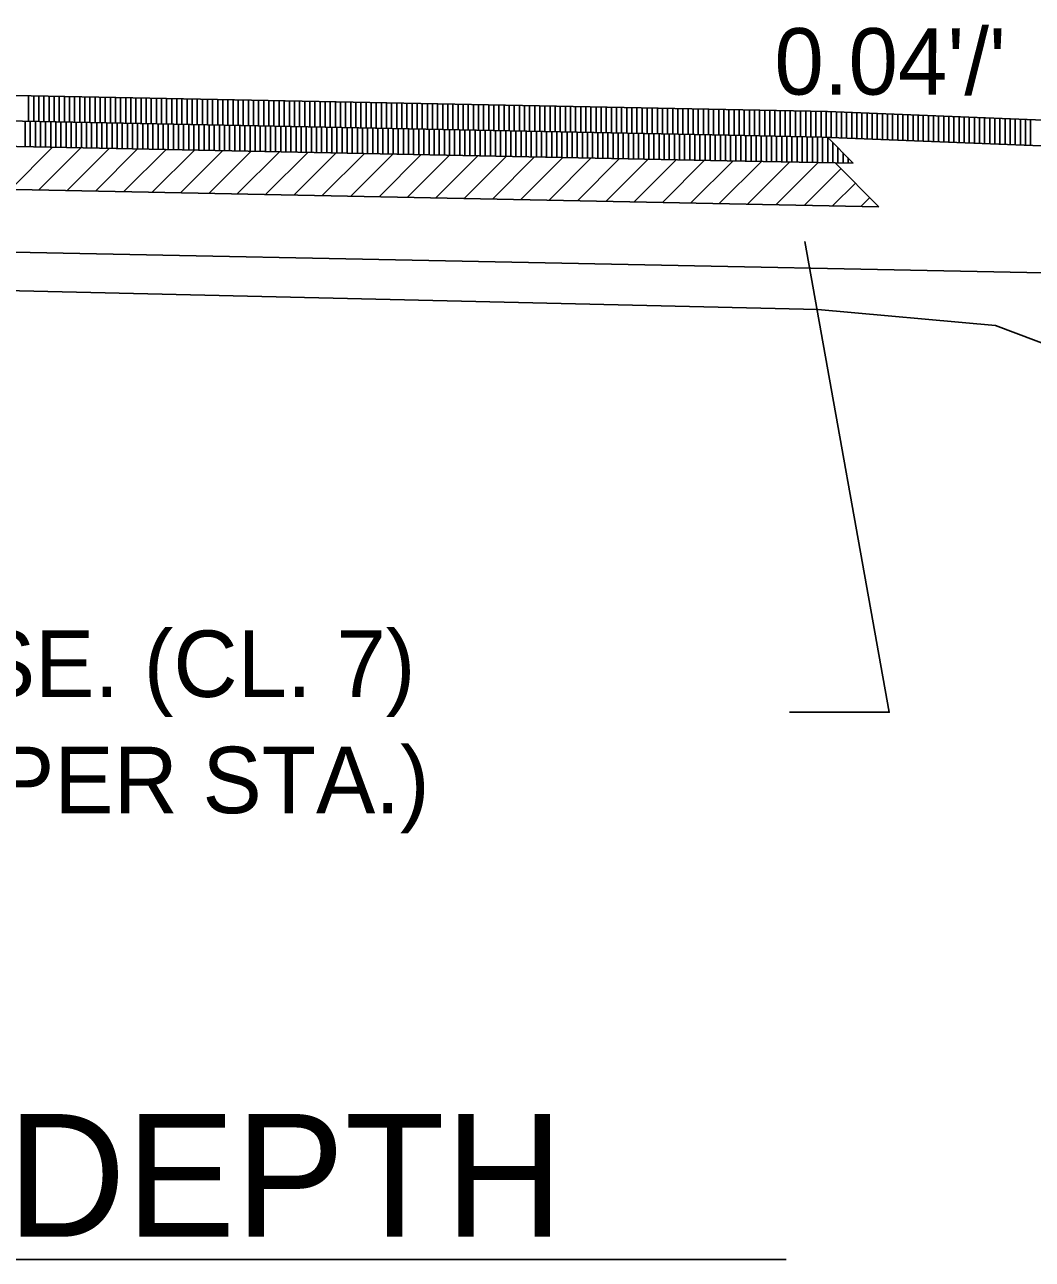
# Model space of a CAD drawing. Extents: x 1373719 to 1374161, y 379835 to 380167.
# Drawn here: x 1373967.86 to 1373977.71, y 380049.16 to 380061.24 of the extents above; entities that cross this region are included whole.
import ezdxf

# ---------------------------------------------------------------- set-up
doc = ezdxf.new("R2010")
doc.units = 0
for name, color, linetype in [('ACHM Surface', 7, 'Continuous'), ('Agg Base Course Text', 7, 'Continuous'), ('Binder', 7, 'Continuous'), ('GREEN_TXT', 7, 'Continuous'), ('T_Drafting', 7, 'Continuous')]:
    doc.layers.add(name, color=color, linetype=linetype)

msp = doc.modelspace()

# ---------------------------------------------------------------- linework, layer by layer
for p, q in [((1373964.712, 380060.605), (1373975.71, 380060.386)), ((1373975.71, 380060.386), (1373979.707, 380060.226)), ((1373975.711, 380060.135), (1373975.964, 380059.881)), ((1373975.785, 380059.885), (1373976.214, 380059.455)), ((1373964.691, 380059.072), (1373986.027, 380058.646))]:
    msp.add_line(p, q)
for points in [[(1373964.712, 380060.355), (1373974.743, 380060.155), (1373975.657, 380060.137), (1373977.8, 380060.052), (1373979.542, 380059.986)], [(1373964.712, 380060.105), (1373974.731, 380059.905), (1373975.964, 380059.881)], [(1373964.682, 380059.685), (1373976.214, 380059.455)]]:
    msp.add_lwpolyline(points)
at = {"layer": 'ACHM Surface'}
for p, q in [((1373967.898, 380060.292), (1373967.898, 380060.542)), ((1373967.948, 380060.291), (1373967.948, 380060.541)), ((1373967.998, 380060.29), (1373967.998, 380060.54)), ((1373968.048, 380060.289), (1373968.048, 380060.539)), ((1373968.098, 380060.288), (1373968.098, 380060.538)), ((1373968.148, 380060.287), (1373968.148, 380060.537)), ((1373968.198, 380060.286), (1373968.198, 380060.536)), ((1373968.248, 380060.285), (1373968.248, 380060.535)), ((1373968.298, 380060.284), (1373968.298, 380060.534)), ((1373968.348, 380060.283), (1373968.348, 380060.533)), ((1373968.398, 380060.282), (1373968.398, 380060.532)), ((1373968.448, 380060.281), (1373968.448, 380060.531)), ((1373968.498, 380060.28), (1373968.498, 380060.53)), ((1373968.548, 380060.279), (1373968.548, 380060.529)), ((1373968.598, 380060.278), (1373968.598, 380060.528)), ((1373968.648, 380060.277), (1373968.648, 380060.527)), ((1373968.698, 380060.276), (1373968.698, 380060.526)), ((1373968.748, 380060.275), (1373968.748, 380060.525)), ((1373968.798, 380060.274), (1373968.798, 380060.524)), ((1373968.848, 380060.273), (1373968.848, 380060.523)), ((1373968.898, 380060.272), (1373968.898, 380060.522)), ((1373968.948, 380060.271), (1373968.948, 380060.521)), ((1373968.998, 380060.27), (1373968.998, 380060.52)), ((1373969.048, 380060.269), (1373969.048, 380060.519)), ((1373969.098, 380060.268), (1373969.098, 380060.518)), ((1373969.148, 380060.267), (1373969.148, 380060.517)), ((1373969.198, 380060.266), (1373969.198, 380060.516)), ((1373969.248, 380060.265), (1373969.248, 380060.515)), ((1373969.298, 380060.264), (1373969.298, 380060.514)), ((1373969.348, 380060.263), (1373969.348, 380060.513)), ((1373969.398, 380060.262), (1373969.398, 380060.512)), ((1373969.448, 380060.261), (1373969.448, 380060.511)), ((1373969.498, 380060.26), (1373969.498, 380060.51)), ((1373969.548, 380060.259), (1373969.548, 380060.509)), ((1373969.598, 380060.258), (1373969.598, 380060.508)), ((1373969.648, 380060.257), (1373969.648, 380060.507)), ((1373969.698, 380060.256), (1373969.698, 380060.506)), ((1373969.748, 380060.255), (1373969.748, 380060.505)), ((1373969.798, 380060.254), (1373969.798, 380060.504)), ((1373969.848, 380060.253), (1373969.848, 380060.503)), ((1373969.898, 380060.252), (1373969.898, 380060.502)), ((1373969.948, 380060.251), (1373969.948, 380060.501)), ((1373969.998, 380060.25), (1373969.998, 380060.5)), ((1373970.048, 380060.249), (1373970.048, 380060.499)), ((1373970.098, 380060.248), (1373970.098, 380060.498)), ((1373970.148, 380060.247), (1373970.148, 380060.497)), ((1373970.198, 380060.246), (1373970.198, 380060.496)), ((1373970.248, 380060.245), (1373970.248, 380060.495)), ((1373970.298, 380060.244), (1373970.298, 380060.494)), ((1373970.348, 380060.243), (1373970.348, 380060.493)), ((1373970.398, 380060.242), (1373970.398, 380060.492)), ((1373970.448, 380060.241), (1373970.448, 380060.491)), ((1373970.498, 380060.24), (1373970.498, 380060.49)), ((1373970.548, 380060.239), (1373970.548, 380060.489)), ((1373970.598, 380060.238), (1373970.598, 380060.488)), ((1373970.648, 380060.237), (1373970.648, 380060.487)), ((1373970.698, 380060.236), (1373970.698, 380060.486)), ((1373970.748, 380060.235), (1373970.748, 380060.485)), ((1373970.798, 380060.234), (1373970.798, 380060.484)), ((1373970.848, 380060.233), (1373970.848, 380060.483)), ((1373970.898, 380060.232), (1373970.898, 380060.482)), ((1373970.948, 380060.231), (1373970.948, 380060.481)), ((1373970.998, 380060.23), (1373970.998, 380060.48)), ((1373971.048, 380060.229), (1373971.048, 380060.479)), ((1373971.098, 380060.228), (1373971.098, 380060.478)), ((1373971.148, 380060.227), (1373971.148, 380060.477)), ((1373971.198, 380060.226), (1373971.198, 380060.476)), ((1373971.248, 380060.225), (1373971.248, 380060.475)), ((1373971.298, 380060.224), (1373971.298, 380060.474)), ((1373971.348, 380060.223), (1373971.348, 380060.473)), ((1373971.398, 380060.222), (1373971.398, 380060.472)), ((1373971.448, 380060.221), (1373971.448, 380060.471)), ((1373971.498, 380060.22), (1373971.498, 380060.47)), ((1373971.548, 380060.219), (1373971.548, 380060.469)), ((1373971.598, 380060.218), (1373971.598, 380060.468)), ((1373971.648, 380060.217), (1373971.648, 380060.467)), ((1373971.698, 380060.216), (1373971.698, 380060.466)), ((1373971.748, 380060.215), (1373971.748, 380060.465)), ((1373971.798, 380060.214), (1373971.798, 380060.464)), ((1373971.848, 380060.213), (1373971.848, 380060.463)), ((1373971.898, 380060.212), (1373971.898, 380060.462)), ((1373971.948, 380060.211), (1373971.948, 380060.461)), ((1373971.998, 380060.21), (1373971.998, 380060.46)), ((1373972.048, 380060.209), (1373972.048, 380060.459)), ((1373972.098, 380060.208), (1373972.098, 380060.458)), ((1373972.148, 380060.207), (1373972.148, 380060.457)), ((1373972.198, 380060.206), (1373972.198, 380060.456)), ((1373972.248, 380060.205), (1373972.248, 380060.455)), ((1373972.298, 380060.204), (1373972.298, 380060.454)), ((1373972.348, 380060.203), (1373972.348, 380060.453)), ((1373972.398, 380060.202), (1373972.398, 380060.452)), ((1373972.448, 380060.201), (1373972.448, 380060.451)), ((1373972.498, 380060.2), (1373972.498, 380060.45)), ((1373972.548, 380060.199), (1373972.548, 380060.449)), ((1373972.598, 380060.198), (1373972.598, 380060.448)), ((1373972.648, 380060.197), (1373972.648, 380060.447)), ((1373972.698, 380060.196), (1373972.698, 380060.446)), ((1373972.748, 380060.195), (1373972.748, 380060.445)), ((1373972.798, 380060.194), (1373972.798, 380060.444)), ((1373972.848, 380060.193), (1373972.848, 380060.443)), ((1373972.898, 380060.192), (1373972.898, 380060.442)), ((1373972.948, 380060.191), (1373972.948, 380060.441)), ((1373972.998, 380060.19), (1373972.998, 380060.44)), ((1373973.048, 380060.189), (1373973.048, 380060.439)), ((1373973.098, 380060.188), (1373973.098, 380060.438)), ((1373973.148, 380060.187), (1373973.148, 380060.437)), ((1373973.198, 380060.186), (1373973.198, 380060.436)), ((1373973.248, 380060.185), (1373973.248, 380060.435)), ((1373973.298, 380060.184), (1373973.298, 380060.434)), ((1373973.348, 380060.183), (1373973.348, 380060.433)), ((1373973.398, 380060.182), (1373973.398, 380060.432)), ((1373973.448, 380060.181), (1373973.448, 380060.431)), ((1373973.498, 380060.18), (1373973.498, 380060.43)), ((1373973.548, 380060.179), (1373973.548, 380060.429)), ((1373973.598, 380060.178), (1373973.598, 380060.428)), ((1373973.648, 380060.177), (1373973.648, 380060.427)), ((1373973.698, 380060.176), (1373973.698, 380060.426)), ((1373973.748, 380060.175), (1373973.748, 380060.425)), ((1373973.798, 380060.174), (1373973.798, 380060.424)), ((1373973.848, 380060.173), (1373973.848, 380060.423)), ((1373973.898, 380060.172), (1373973.898, 380060.422)), ((1373973.948, 380060.171), (1373973.948, 380060.421)), ((1373973.998, 380060.17), (1373973.998, 380060.42)), ((1373974.048, 380060.169), (1373974.048, 380060.419)), ((1373974.098, 380060.168), (1373974.098, 380060.418)), ((1373974.148, 380060.167), (1373974.148, 380060.417)), ((1373974.198, 380060.166), (1373974.198, 380060.416)), ((1373974.248, 380060.165), (1373974.248, 380060.415)), ((1373974.298, 380060.164), (1373974.298, 380060.414)), ((1373974.348, 380060.163), (1373974.348, 380060.413)), ((1373974.398, 380060.162), (1373974.398, 380060.412)), ((1373967.864, 380060.042), (1373967.864, 380060.293)), ((1373967.914, 380060.041), (1373967.914, 380060.292)), ((1373967.964, 380060.04), (1373967.964, 380060.291)), ((1373974.448, 380060.161), (1373974.448, 380060.411)), ((1373974.498, 380060.16), (1373974.498, 380060.41)), ((1373974.548, 380060.159), (1373974.548, 380060.409)), ((1373974.598, 380060.158), (1373974.598, 380060.408)), ((1373974.648, 380060.157), (1373974.648, 380060.407)), ((1373974.698, 380060.156), (1373974.698, 380060.406)), ((1373974.748, 380060.155), (1373974.748, 380060.405)), ((1373974.798, 380060.154), (1373974.798, 380060.404)), ((1373974.848, 380060.153), (1373974.848, 380060.403)), ((1373974.898, 380060.152), (1373974.898, 380060.402)), ((1373974.948, 380060.151), (1373974.948, 380060.401)), ((1373974.998, 380060.15), (1373974.998, 380060.4)), ((1373975.048, 380060.149), (1373975.048, 380060.399)), ((1373975.098, 380060.148), (1373975.098, 380060.398)), ((1373975.148, 380060.147), (1373975.148, 380060.397)), ((1373975.198, 380060.146), (1373975.198, 380060.396)), ((1373975.248, 380060.145), (1373975.248, 380060.395)), ((1373975.298, 380060.144), (1373975.298, 380060.394)), ((1373975.348, 380060.143), (1373975.348, 380060.393)), ((1373975.398, 380060.142), (1373975.398, 380060.392)), ((1373975.448, 380060.141), (1373975.448, 380060.391)), ((1373975.498, 380060.14), (1373975.498, 380060.39)), ((1373975.548, 380060.139), (1373975.548, 380060.389)), ((1373975.598, 380060.138), (1373975.598, 380060.388)), ((1373975.648, 380060.137), (1373975.648, 380060.387)), ((1373975.698, 380060.135), (1373975.698, 380060.386)), ((1373975.748, 380060.133), (1373975.748, 380060.384)), ((1373975.798, 380060.131), (1373975.798, 380060.382)), ((1373975.848, 380060.129), (1373975.848, 380060.38)), ((1373975.898, 380060.127), (1373975.898, 380060.378)), ((1373975.948, 380060.126), (1373975.948, 380060.376)), ((1373975.998, 380060.124), (1373975.998, 380060.374)), ((1373976.048, 380060.122), (1373976.048, 380060.372)), ((1373976.098, 380060.12), (1373976.098, 380060.37)), ((1373976.148, 380060.118), (1373976.148, 380060.368)), ((1373976.198, 380060.116), (1373976.198, 380060.366)), ((1373976.248, 380060.114), (1373976.248, 380060.364)), ((1373976.298, 380060.112), (1373976.298, 380060.362)), ((1373976.348, 380060.11), (1373976.348, 380060.36)), ((1373976.398, 380060.108), (1373976.398, 380060.358)), ((1373976.448, 380060.106), (1373976.448, 380060.356)), ((1373976.498, 380060.104), (1373976.498, 380060.354)), ((1373976.548, 380060.102), (1373976.548, 380060.352)), ((1373976.598, 380060.1), (1373976.598, 380060.35)), ((1373976.648, 380060.098), (1373976.648, 380060.348)), ((1373976.698, 380060.096), (1373976.698, 380060.346)), ((1373976.748, 380060.094), (1373976.748, 380060.344)), ((1373976.798, 380060.092), (1373976.798, 380060.342)), ((1373976.848, 380060.09), (1373976.848, 380060.34)), ((1373976.898, 380060.088), (1373976.898, 380060.338)), ((1373976.948, 380060.086), (1373976.948, 380060.336)), ((1373976.998, 380060.084), (1373976.998, 380060.334)), ((1373977.048, 380060.082), (1373977.048, 380060.332)), ((1373977.098, 380060.08), (1373977.098, 380060.33)), ((1373977.148, 380060.078), (1373977.148, 380060.328)), ((1373977.198, 380060.076), (1373977.198, 380060.326)), ((1373977.248, 380060.074), (1373977.248, 380060.324)), ((1373977.298, 380060.072), (1373977.298, 380060.322)), ((1373977.348, 380060.07), (1373977.348, 380060.32)), ((1373977.398, 380060.068), (1373977.398, 380060.318)), ((1373977.448, 380060.066), (1373977.448, 380060.316)), ((1373977.498, 380060.064), (1373977.498, 380060.314)), ((1373977.548, 380060.062), (1373977.548, 380060.312)), ((1373977.598, 380060.06), (1373977.598, 380060.31)), ((1373977.648, 380060.058), (1373977.648, 380060.308)), ((1373977.698, 380060.056), (1373977.698, 380060.306)), ((1373968.014, 380060.039), (1373968.014, 380060.29)), ((1373968.064, 380060.038), (1373968.064, 380060.289)), ((1373968.114, 380060.037), (1373968.114, 380060.288)), ((1373968.164, 380060.036), (1373968.164, 380060.287)), ((1373968.214, 380060.035), (1373968.214, 380060.286)), ((1373968.264, 380060.034), (1373968.264, 380060.285)), ((1373968.314, 380060.033), (1373968.314, 380060.284)), ((1373968.364, 380060.032), (1373968.364, 380060.283)), ((1373968.414, 380060.031), (1373968.414, 380060.282)), ((1373968.464, 380060.03), (1373968.464, 380060.281)), ((1373968.514, 380060.029), (1373968.514, 380060.28)), ((1373968.564, 380060.028), (1373968.564, 380060.279)), ((1373968.614, 380060.027), (1373968.614, 380060.278)), ((1373968.664, 380060.026), (1373968.664, 380060.277)), ((1373968.714, 380060.025), (1373968.714, 380060.276)), ((1373968.764, 380060.024), (1373968.764, 380060.275)), ((1373968.814, 380060.023), (1373968.814, 380060.274)), ((1373968.864, 380060.022), (1373968.864, 380060.273)), ((1373968.914, 380060.021), (1373968.914, 380060.272)), ((1373968.964, 380060.02), (1373968.964, 380060.271)), ((1373969.014, 380060.019), (1373969.014, 380060.27)), ((1373969.064, 380060.018), (1373969.064, 380060.269)), ((1373969.114, 380060.017), (1373969.114, 380060.268)), ((1373969.164, 380060.016), (1373969.164, 380060.267)), ((1373969.214, 380060.015), (1373969.214, 380060.266)), ((1373969.264, 380060.014), (1373969.264, 380060.265)), ((1373969.314, 380060.013), (1373969.314, 380060.264)), ((1373969.364, 380060.012), (1373969.364, 380060.263)), ((1373969.414, 380060.011), (1373969.414, 380060.262)), ((1373969.464, 380060.01), (1373969.464, 380060.261)), ((1373969.514, 380060.009), (1373969.514, 380060.26)), ((1373969.564, 380060.008), (1373969.564, 380060.259)), ((1373969.614, 380060.007), (1373969.614, 380060.258)), ((1373969.664, 380060.006), (1373969.664, 380060.257)), ((1373969.714, 380060.005), (1373969.714, 380060.256)), ((1373969.764, 380060.004), (1373969.764, 380060.255)), ((1373969.814, 380060.003), (1373969.814, 380060.254)), ((1373969.864, 380060.002), (1373969.864, 380060.253)), ((1373969.914, 380060.001), (1373969.914, 380060.252)), ((1373969.964, 380060), (1373969.964, 380060.251)), ((1373970.014, 380059.999), (1373970.014, 380060.25)), ((1373970.064, 380059.998), (1373970.064, 380060.249)), ((1373970.114, 380059.997), (1373970.114, 380060.248)), ((1373970.164, 380059.996), (1373970.164, 380060.247)), ((1373970.214, 380059.995), (1373970.214, 380060.246)), ((1373970.264, 380059.994), (1373970.264, 380060.245)), ((1373970.314, 380059.993), (1373970.314, 380060.244)), ((1373970.364, 380059.992), (1373970.364, 380060.243)), ((1373970.414, 380059.991), (1373970.414, 380060.242)), ((1373970.464, 380059.99), (1373970.464, 380060.241)), ((1373970.514, 380059.989), (1373970.514, 380060.24)), ((1373970.564, 380059.988), (1373970.564, 380060.239)), ((1373970.614, 380059.987), (1373970.614, 380060.238)), ((1373970.664, 380059.986), (1373970.664, 380060.237)), ((1373970.714, 380059.985), (1373970.714, 380060.236)), ((1373970.764, 380059.984), (1373970.764, 380060.234)), ((1373970.814, 380059.983), (1373970.814, 380060.233)), ((1373970.864, 380059.982), (1373970.864, 380060.232)), ((1373970.914, 380059.981), (1373970.914, 380060.231)), ((1373970.964, 380059.98), (1373970.964, 380060.23)), ((1373971.014, 380059.979), (1373971.014, 380060.229)), ((1373971.064, 380059.978), (1373971.064, 380060.228)), ((1373971.114, 380059.977), (1373971.114, 380060.227)), ((1373971.164, 380059.976), (1373971.164, 380060.226)), ((1373971.214, 380059.975), (1373971.214, 380060.225)), ((1373971.264, 380059.974), (1373971.264, 380060.224)), ((1373971.314, 380059.973), (1373971.314, 380060.223)), ((1373971.364, 380059.972), (1373971.364, 380060.222)), ((1373971.414, 380059.971), (1373971.414, 380060.221)), ((1373971.464, 380059.97), (1373971.464, 380060.22)), ((1373971.514, 380059.969), (1373971.514, 380060.219)), ((1373971.564, 380059.968), (1373971.564, 380060.218)), ((1373971.614, 380059.967), (1373971.614, 380060.217)), ((1373971.664, 380059.966), (1373971.664, 380060.216)), ((1373971.714, 380059.965), (1373971.714, 380060.215)), ((1373971.764, 380059.964), (1373971.764, 380060.214)), ((1373971.814, 380059.963), (1373971.814, 380060.213)), ((1373971.864, 380059.962), (1373971.864, 380060.212)), ((1373971.914, 380059.961), (1373971.914, 380060.211)), ((1373971.964, 380059.96), (1373971.964, 380060.21)), ((1373972.014, 380059.959), (1373972.014, 380060.209)), ((1373972.064, 380059.958), (1373972.064, 380060.208)), ((1373972.114, 380059.957), (1373972.114, 380060.207)), ((1373972.164, 380059.956), (1373972.164, 380060.206)), ((1373972.214, 380059.955), (1373972.214, 380060.205)), ((1373972.264, 380059.954), (1373972.264, 380060.204)), ((1373972.314, 380059.953), (1373972.314, 380060.203)), ((1373972.364, 380059.952), (1373972.364, 380060.202)), ((1373972.414, 380059.951), (1373972.414, 380060.201)), ((1373972.464, 380059.95), (1373972.464, 380060.2)), ((1373972.514, 380059.949), (1373972.514, 380060.199)), ((1373972.564, 380059.948), (1373972.564, 380060.198)), ((1373972.614, 380059.947), (1373972.614, 380060.197)), ((1373972.664, 380059.946), (1373972.664, 380060.196)), ((1373972.714, 380059.945), (1373972.714, 380060.195)), ((1373972.764, 380059.944), (1373972.764, 380060.194)), ((1373972.814, 380059.943), (1373972.814, 380060.193)), ((1373972.864, 380059.942), (1373972.864, 380060.192)), ((1373972.914, 380059.941), (1373972.914, 380060.191)), ((1373972.964, 380059.94), (1373972.964, 380060.19)), ((1373973.014, 380059.939), (1373973.014, 380060.189)), ((1373973.064, 380059.938), (1373973.064, 380060.188)), ((1373973.114, 380059.937), (1373973.114, 380060.187)), ((1373973.164, 380059.936), (1373973.164, 380060.186)), ((1373973.214, 380059.935), (1373973.214, 380060.185)), ((1373973.264, 380059.934), (1373973.264, 380060.184)), ((1373973.314, 380059.933), (1373973.314, 380060.183)), ((1373973.364, 380059.932), (1373973.364, 380060.182)), ((1373973.414, 380059.931), (1373973.414, 380060.181)), ((1373973.464, 380059.93), (1373973.464, 380060.18)), ((1373973.514, 380059.929), (1373973.514, 380060.179)), ((1373973.564, 380059.928), (1373973.564, 380060.178)), ((1373973.614, 380059.927), (1373973.614, 380060.177)), ((1373973.664, 380059.926), (1373973.664, 380060.176)), ((1373973.714, 380059.925), (1373973.714, 380060.175)), ((1373973.764, 380059.924), (1373973.764, 380060.174)), ((1373973.814, 380059.923), (1373973.814, 380060.173)), ((1373973.864, 380059.922), (1373973.864, 380060.172)), ((1373973.914, 380059.921), (1373973.914, 380060.171)), ((1373973.964, 380059.92), (1373973.964, 380060.17)), ((1373974.014, 380059.919), (1373974.014, 380060.169)), ((1373974.064, 380059.918), (1373974.064, 380060.168)), ((1373974.114, 380059.917), (1373974.114, 380060.167)), ((1373974.164, 380059.916), (1373974.164, 380060.166)), ((1373974.214, 380059.915), (1373974.214, 380060.165)), ((1373974.264, 380059.914), (1373974.264, 380060.164)), ((1373974.314, 380059.913), (1373974.314, 380060.163)), ((1373974.364, 380059.912), (1373974.364, 380060.162)), ((1373974.414, 380059.911), (1373974.414, 380060.161)), ((1373974.464, 380059.91), (1373974.464, 380060.16)), ((1373974.514, 380059.909), (1373974.514, 380060.159)), ((1373974.564, 380059.908), (1373974.564, 380060.158)), ((1373974.614, 380059.907), (1373974.614, 380060.157)), ((1373974.664, 380059.906), (1373974.664, 380060.156)), ((1373974.714, 380059.905), (1373974.714, 380060.155)), ((1373974.764, 380059.904), (1373974.764, 380060.154)), ((1373974.814, 380059.903), (1373974.814, 380060.153)), ((1373974.864, 380059.903), (1373974.864, 380060.153)), ((1373974.914, 380059.902), (1373974.914, 380060.152)), ((1373974.964, 380059.901), (1373974.964, 380060.151)), ((1373975.014, 380059.9), (1373975.014, 380060.15)), ((1373975.064, 380059.899), (1373975.064, 380060.149)), ((1373975.114, 380059.898), (1373975.114, 380060.148)), ((1373975.164, 380059.897), (1373975.164, 380060.147)), ((1373975.214, 380059.896), (1373975.214, 380060.146)), ((1373975.264, 380059.895), (1373975.264, 380060.145)), ((1373975.314, 380059.894), (1373975.314, 380060.144)), ((1373975.364, 380059.893), (1373975.364, 380060.143)), ((1373975.414, 380059.892), (1373975.414, 380060.142)), ((1373975.464, 380059.891), (1373975.464, 380060.141)), ((1373975.514, 380059.89), (1373975.514, 380060.14)), ((1373975.564, 380059.889), (1373975.564, 380060.139)), ((1373975.614, 380059.888), (1373975.614, 380060.138)), ((1373975.664, 380059.886), (1373975.664, 380060.137)), ((1373975.714, 380059.884), (1373975.714, 380060.132)), ((1373975.764, 380059.885), (1373975.764, 380060.082)), ((1373975.814, 380059.884), (1373975.814, 380060.032)), ((1373975.864, 380059.883), (1373975.864, 380059.982)), ((1373975.914, 380059.882), (1373975.914, 380059.932)), ((1373975.964, 380059.881), (1373975.964, 380059.882))]:
    msp.add_line(p, q, dxfattribs=at)
at = {"layer": 'Agg Base Course Text'}
msp.add_lwpolyline([(1373975.34, 380054.512), (1373976.315, 380054.512), (1373975.489, 380059.114)], dxfattribs=at)
at = {"layer": 'Binder'}
for p, q in [((1373967.72, 380059.625), (1373968.133, 380060.037)), ((1373967.997, 380059.619), (1373968.41, 380060.032)), ((1373968.275, 380059.614), (1373968.687, 380060.026)), ((1373968.552, 380059.608), (1373968.964, 380060.02)), ((1373968.829, 380059.603), (1373969.242, 380060.015)), ((1373969.107, 380059.597), (1373969.519, 380060.009)), ((1373969.384, 380059.591), (1373969.796, 380060.004)), ((1373969.661, 380059.586), (1373970.074, 380059.998)), ((1373969.939, 380059.58), (1373970.351, 380059.993)), ((1373970.216, 380059.575), (1373970.628, 380059.987)), ((1373970.493, 380059.569), (1373970.905, 380059.982)), ((1373970.77, 380059.564), (1373971.183, 380059.976)), ((1373971.048, 380059.558), (1373971.46, 380059.971)), ((1373971.325, 380059.553), (1373971.737, 380059.965)), ((1373971.602, 380059.547), (1373972.015, 380059.959)), ((1373971.88, 380059.542), (1373972.292, 380059.954)), ((1373972.157, 380059.536), (1373972.569, 380059.948)), ((1373972.434, 380059.53), (1373972.847, 380059.943)), ((1373972.711, 380059.525), (1373973.124, 380059.937)), ((1373972.989, 380059.519), (1373973.401, 380059.932)), ((1373973.266, 380059.514), (1373973.678, 380059.926)), ((1373973.543, 380059.508), (1373973.956, 380059.921)), ((1373973.821, 380059.503), (1373974.233, 380059.915)), ((1373974.098, 380059.497), (1373974.51, 380059.91)), ((1373974.375, 380059.492), (1373974.788, 380059.904)), ((1373974.653, 380059.486), (1373975.065, 380059.899)), ((1373974.93, 380059.481), (1373975.343, 380059.893)), ((1373975.207, 380059.475), (1373975.62, 380059.888)), ((1373975.485, 380059.47), (1373975.842, 380059.827)), ((1373975.762, 380059.464), (1373975.984, 380059.686)), ((1373976.039, 380059.458), (1373976.125, 380059.544))]:
    msp.add_line(p, q, dxfattribs=at)
at = {"layer": 'GREEN_TXT'}
msp.add_line((1373954.178, 380049.161), (1373975.306, 380049.161), dxfattribs=at)
at = {"layer": 'T_Drafting'}
msp.add_lwpolyline([(1373907.681, 380053.139), (1373924.228, 380053.063), (1373943.144, 380055.229), (1373951.911, 380058.525), (1373953.6, 380058.693), (1373964.739, 380058.703), (1373975.617, 380058.451), (1373977.355, 380058.293), (1373984.395, 380055.639), (1373996.459, 380059.551), (1374008.612, 380060.525), (1374021.604, 380060.525)], dxfattribs=at)

# ---------------------------------------------------------------- texts
at = {"layer": 'GREEN_TXT'}
msp.add_text("0.04'/'", height=0.65, rotation=359.98, dxfattribs=at).set_placement((1373975.192, 380060.552))
for s, height, p in [('24\'-0" AGGREGATE BASE CRSE. (CL. 7)', 0.65, (1373955.363, 380054.661)), ('6" COMP\'D DEPTH (93.25 TONS PER STA.)', 0.65, (1373954.344, 380053.524)), ('HWY. 115 - FULL DEPTH', 1.2, (1373954.581, 380049.382))]:
    msp.add_text(s, height=height, dxfattribs=at).set_placement(p)

doc.saveas('drawing.dxf')
